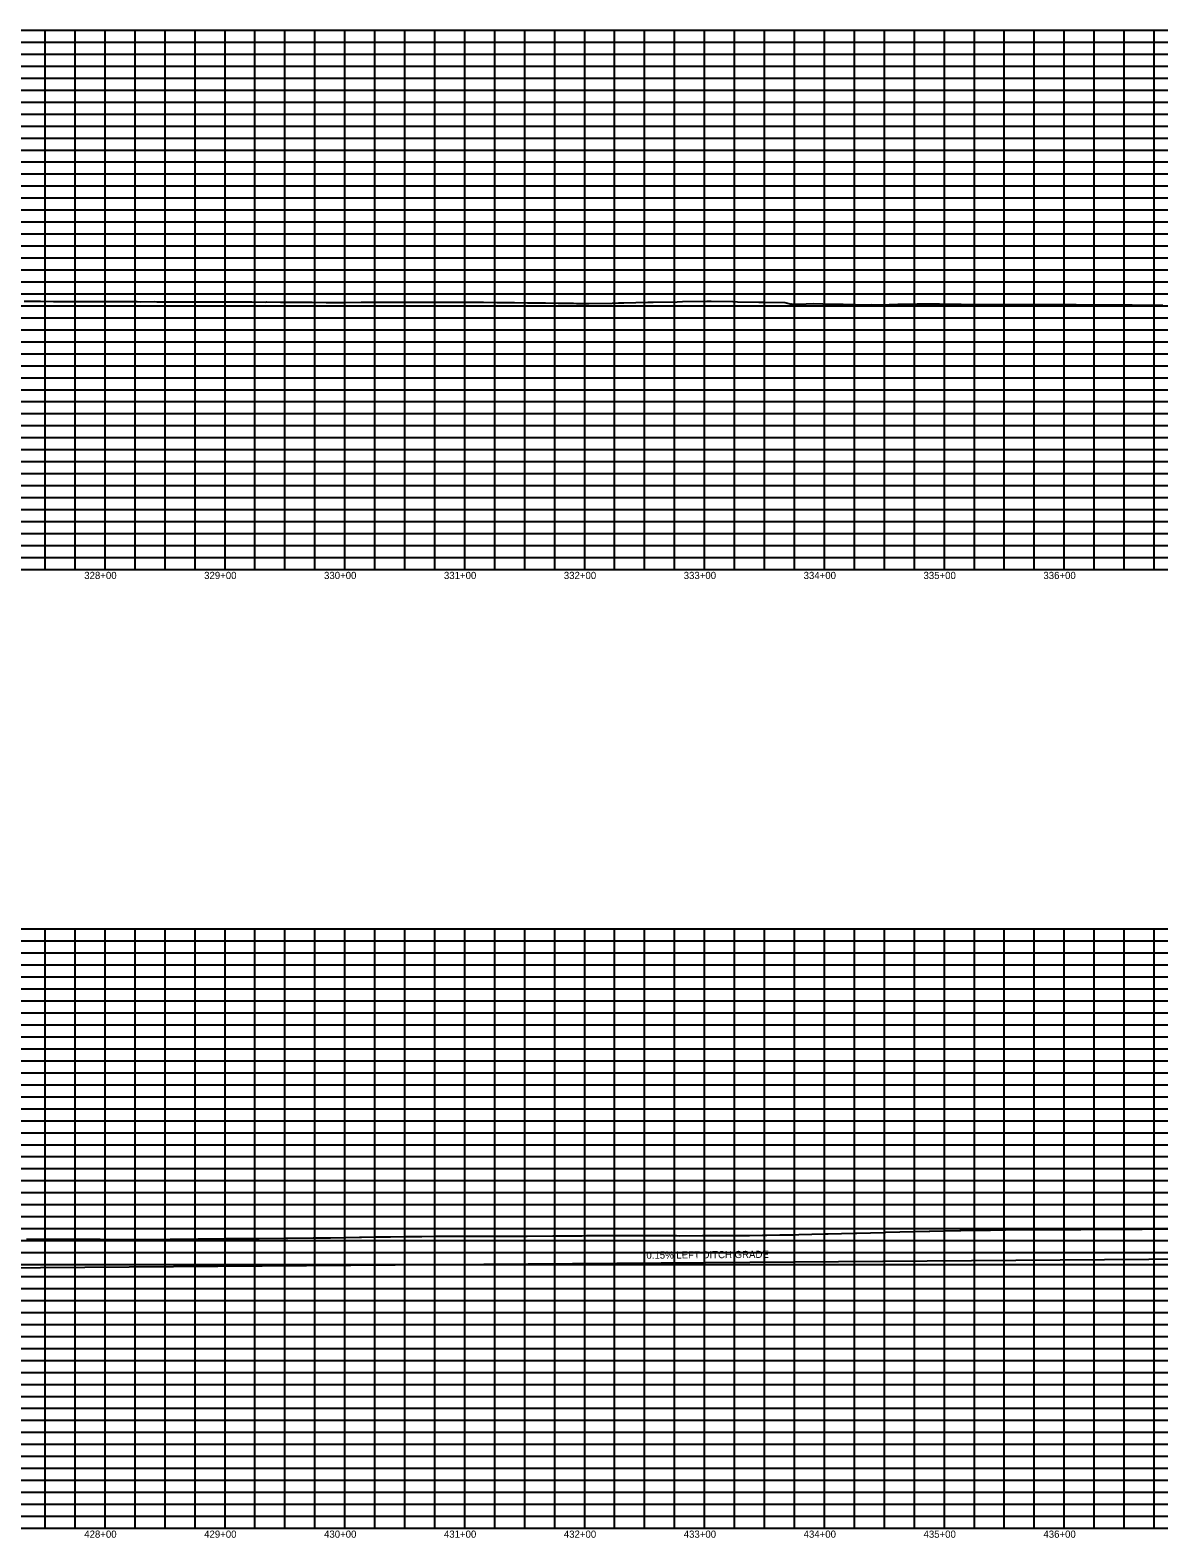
# Model space of a CAD drawing. Extents: x 1399671 to 1408349, y 1930471 to 1933387.
# Drawn here: x 1403062 to 1404003, y 1930471 to 1931729 of the extents above; entities that cross this region are included whole.
import ezdxf

# ---------------------------------------------------------------- set-up
doc = ezdxf.new("R2010")
doc.units = 0
for name, color, linetype in [('R_Exist Surface', 7, 'Continuous'), ('R_Grid', 7, 'Continuous'), ('R_Grid Annot', 7, 'Continuous'), ('R_Vert Alg', 7, 'Continuous'), ('R_Vert Alg Annot', 7, 'Continuous')]:
    doc.layers.add(name, color=color, linetype=linetype)

msp = doc.modelspace()

# ---------------------------------------------------------------- linework, layer by layer
at = {"layer": 'R_Exist Surface'}
for points in [[(1403056.7, 1931502.4), (1403067.6, 1931502.4), (1403070.2, 1931502.4), (1403081.2, 1931502.3), (1403083.8, 1931502.3), (1403094.8, 1931502.3), (1403097.4, 1931502.2), (1403108.8, 1931502.2), (1403111.4, 1931502.2), (1403122.9, 1931502.2), (1403125.4, 1931502.1), (1403136.9, 1931502.1), (1403139.4, 1931502.1), (1403150.9, 1931502.1), (1403153.4, 1931502), (1403165, 1931502.1), (1403167.4, 1931502), (1403179, 1931502), (1403181.4, 1931502), (1403193, 1931502), (1403204.8, 1931502), (1403207.1, 1931502), (1403217.8, 1931501.9), (1403219.7, 1931501.9), (1403230.7, 1931501.8), (1403232.4, 1931501.9), (1403243.5, 1931501.8), (1403245.1, 1931501.8), (1403246.6, 1931501.8), (1403257.8, 1931501.7), (1403259.1, 1931501.8), (1403270.4, 1931501.7), (1403271.7, 1931501.7), (1403283.1, 1931501.6), (1403284.2, 1931501.6), (1403295.8, 1931501.5), (1403296.8, 1931501.5), (1403308.5, 1931501.4), (1403309.5, 1931501.4), (1403323.1, 1931501.4), (1403324.2, 1931501.4), (1403337.7, 1931501.5), (1403339, 1931501.5), (1403352.3, 1931501.5), (1403353.7, 1931501.5), (1403367, 1931501.6), (1403368.4, 1931501.5), (1403381.6, 1931501.6), (1403383.1, 1931501.6), (1403396.2, 1931501.6), (1403397.8, 1931501.6), (1403410.8, 1931501.7), (1403412.5, 1931501.7), (1403425.4, 1931501.7), (1403427.1, 1931501.7), (1403438.2, 1931501.6), (1403439.9, 1931501.5), (1403451, 1931501.4), (1403452.8, 1931501.4), (1403463.8, 1931501.3), (1403465.7, 1931501.3), (1403476.5, 1931501.2), (1403478.7, 1931501.1), (1403489.3, 1931501), (1403491.6, 1931501), (1403502.1, 1931500.9), (1403504.5, 1931500.8), (1403514.9, 1931500.7), (1403517.5, 1931500.6), (1403527.7, 1931500.6), (1403547.2, 1931500.9), (1403552.3, 1931501.1), (1403556.9, 1931501.2), (1403576.9, 1931501.5), (1403581.3, 1931501.7), (1403601.4, 1931502), (1403605.8, 1931502.1), (1403626, 1931502.5), (1403629.7, 1931502.4), (1403647.8, 1931502.1), (1403651.7, 1931502), (1403669.4, 1931501.7), (1403673.6, 1931501.6), (1403691, 1931501.3), (1403695.7, 1931500.1), (1403696.3, 1931500), (1403697.1, 1931500.2), (1403703, 1931500), (1403714.7, 1931500.5), (1403722.7, 1931500.2), (1403731.6, 1931499.9), (1403739.8, 1931500), (1403750, 1931499.6), (1403755, 1931499.5), (1403763.8, 1931499.8), (1403770.4, 1931499.5), (1403778.2, 1931499.7), (1403785.5, 1931500), (1403794.4, 1931500), (1403801.6, 1931500.2), (1403810.9, 1931500.2), (1403820.1, 1931500.1), (1403830.1, 1931499.9), (1403838.3, 1931499.9), (1403848.7, 1931499.8), (1403856.3, 1931499.8), (1403867.1, 1931499.7), (1403872.9, 1931499.7), (1403881.6, 1931499.6), (1403888.9, 1931499.7), (1403896.5, 1931499.6), (1403905.2, 1931499.6), (1403912, 1931499.6), (1403917.6, 1931499.6), (1403927.8, 1931499.6), (1403934.2, 1931499.6), (1403946, 1931499.5), (1403953.6, 1931499.5), (1403963.6, 1931499.4), (1403972.4, 1931499.3), (1403980.8, 1931499.3), (1403990.5, 1931499.2), (1403998.1, 1931499.2), (1404006.3, 1931499.2)], [(1403058.5, 1930719.7), (1403069.5, 1930719.7), (1403071.1, 1930719.7), (1403082.2, 1930719.7), (1403083.8, 1930719.7), (1403094.9, 1930719.7), (1403096.5, 1930719.7), (1403107.5, 1930719.7), (1403118.6, 1930719.7), (1403120.2, 1930719.7), (1403131.3, 1930719.6), (1403133, 1930719.6), (1403144, 1930719.6), (1403145.7, 1930719.6), (1403156.7, 1930719.5), (1403158.4, 1930719.5), (1403178.5, 1930719.8), (1403181.7, 1930719.8), (1403201.8, 1930720.1), (1403204.9, 1930720.1), (1403224.1, 1930720.2), (1403227, 1930720.2), (1403229.9, 1930720.3), (1403249.2, 1930720.4), (1403252.6, 1930720.4), (1403273.5, 1930720.6), (1403276.7, 1930720.6), (1403297.8, 1930720.8), (1403299.3, 1930720.8), (1403310.6, 1930721), (1403312.2, 1930721), (1403323.4, 1930721.2), (1403325.1, 1930721.2), (1403336.3, 1930721.4), (1403338.1, 1930721.4), (1403349.1, 1930721.6), (1403351.1, 1930721.6), (1403362.2, 1930721.7), (1403373.5, 1930721.9), (1403375.4, 1930721.9), (1403386.6, 1930722), (1403388.5, 1930722), (1403399.8, 1930722.2), (1403401.7, 1930722.2), (1403421.4, 1930722.2), (1403424.7, 1930722.2), (1403444.3, 1930722.2), (1403447.6, 1930722.2), (1403451.4, 1930722.3), (1403472.6, 1930722.3), (1403476.3, 1930722.3), (1403497.5, 1930722.4), (1403501.2, 1930722.4), (1403522.1, 1930722.6), (1403525.6, 1930722.7), (1403546.6, 1930722.9), (1403548.7, 1930722.9), (1403560.7, 1930722.8), (1403562.9, 1930722.8), (1403574.9, 1930722.8), (1403586.7, 1930722.7), (1403589, 1930722.7), (1403600.8, 1930722.7), (1403603.1, 1930722.6), (1403622.4, 1930722.7), (1403626.1, 1930722.7), (1403645.5, 1930722.7), (1403649, 1930722.8), (1403659.9, 1930722.9), (1403661.7, 1930722.9), (1403672.6, 1930723.1), (1403674.4, 1930723.1), (1403676, 1930723.1), (1403687.1, 1930723.3), (1403688.6, 1930723.3), (1403699.7, 1930723.5), (1403702.7, 1930723.6), (1403724.6, 1930724.1), (1403727.3, 1930724.2), (1403749.5, 1930724.7), (1403751.3, 1930724.7), (1403774.1, 1930725.4), (1403775.4, 1930725.5), (1403798.8, 1930726.2), (1403799.5, 1930726.2), (1403811.5, 1930726.4), (1403812.1, 1930726.4), (1403824.3, 1930726.7), (1403825, 1930726.7), (1403837.1, 1930727), (1403837.8, 1930727), (1403849.9, 1930727.2), (1403862.3, 1930727.4), (1403862.6, 1930727.4), (1403875, 1930727.5), (1403875.2, 1930727.5), (1403887.7, 1930727.7), (1403887.9, 1930727.7), (1403900.4, 1930727.9), (1403900.5, 1930727.9), (1403912.8, 1930727.9), (1403913.2, 1930727.9), (1403925.6, 1930727.9), (1403937.8, 1930727.9), (1403938.4, 1930728), (1403950.6, 1930728), (1403950.9, 1930728), (1403963.5, 1930728.1), (1403976, 1930728.1), (1403976.4, 1930728.1), (1403988.9, 1930728.2), (1403989.3, 1930728.2), (1404001.8, 1930728.3), (1404002.2, 1930728.3), (1404025.6, 1930728.2)]]:
    msp.add_lwpolyline(points, dxfattribs=at)
at = {"layer": 'R_Grid'}
for p, q in [((1400324.2, 1931728.6), (1408324.2, 1931728.6)), ((1400324.2, 1931728.6), (1408324.2, 1931728.6)), ((1403074.2, 1931278.6), (1403074.2, 1931728.6)), ((1403099.2, 1931278.6), (1403099.2, 1931728.6)), ((1403124.2, 1931278.6), (1403124.2, 1931728.6)), ((1403149.2, 1931278.6), (1403149.2, 1931728.6)), ((1403174.2, 1931278.6), (1403174.2, 1931728.6)), ((1403199.2, 1931278.6), (1403199.2, 1931728.6)), ((1403224.2, 1931278.6), (1403224.2, 1931728.6)), ((1403249.2, 1931278.6), (1403249.2, 1931728.6)), ((1403274.2, 1931278.6), (1403274.2, 1931728.6)), ((1403299.2, 1931278.6), (1403299.2, 1931728.6)), ((1403324.2, 1931278.6), (1403324.2, 1931728.6)), ((1403349.2, 1931278.6), (1403349.2, 1931728.6)), ((1403374.2, 1931278.6), (1403374.2, 1931728.6)), ((1403399.2, 1931278.6), (1403399.2, 1931728.6)), ((1403424.2, 1931278.6), (1403424.2, 1931728.6)), ((1403449.2, 1931278.6), (1403449.2, 1931728.6)), ((1403474.2, 1931278.6), (1403474.2, 1931728.6)), ((1403499.2, 1931278.6), (1403499.2, 1931728.6)), ((1403524.2, 1931278.6), (1403524.2, 1931728.6)), ((1403549.2, 1931278.6), (1403549.2, 1931728.6)), ((1403574.2, 1931278.6), (1403574.2, 1931728.6)), ((1403599.2, 1931278.6), (1403599.2, 1931728.6)), ((1403624.2, 1931278.6), (1403624.2, 1931728.6)), ((1403649.2, 1931278.6), (1403649.2, 1931728.6)), ((1403674.2, 1931278.6), (1403674.2, 1931728.6)), ((1403699.2, 1931278.6), (1403699.2, 1931728.6)), ((1403724.2, 1931278.6), (1403724.2, 1931728.6)), ((1403749.2, 1931278.6), (1403749.2, 1931728.6)), ((1403774.2, 1931278.6), (1403774.2, 1931728.6)), ((1403799.2, 1931278.6), (1403799.2, 1931728.6)), ((1403824.2, 1931278.6), (1403824.2, 1931728.6)), ((1403849.2, 1931278.6), (1403849.2, 1931728.6)), ((1403874.2, 1931278.6), (1403874.2, 1931728.6)), ((1403899.2, 1931278.6), (1403899.2, 1931728.6)), ((1403924.2, 1931278.6), (1403924.2, 1931728.6)), ((1403949.2, 1931278.6), (1403949.2, 1931728.6)), ((1403974.2, 1931278.6), (1403974.2, 1931728.6)), ((1403999.2, 1931278.6), (1403999.2, 1931728.6)), ((1400324.2, 1931718.6), (1408324.2, 1931718.6)), ((1400324.2, 1931708.6), (1408324.2, 1931708.6)), ((1400324.2, 1931698.6), (1408324.2, 1931698.6)), ((1400324.2, 1931688.6), (1408324.2, 1931688.6)), ((1400324.2, 1931678.6), (1408324.2, 1931678.6)), ((1400324.2, 1931668.6), (1408324.2, 1931668.6)), ((1400324.2, 1931658.6), (1408324.2, 1931658.6)), ((1400324.2, 1931648.6), (1408324.2, 1931648.6)), ((1400324.2, 1931638.6), (1408324.2, 1931638.6)), ((1400324.2, 1931628.6), (1408324.2, 1931628.6)), ((1400324.2, 1931618.6), (1408324.2, 1931618.6)), ((1400324.2, 1931608.6), (1408324.2, 1931608.6)), ((1400324.2, 1931598.6), (1408324.2, 1931598.6)), ((1400324.2, 1931588.6), (1408324.2, 1931588.6)), ((1400324.2, 1931578.6), (1408324.2, 1931578.6)), ((1400324.2, 1931568.6), (1408324.2, 1931568.6)), ((1400324.2, 1931558.6), (1408324.2, 1931558.6)), ((1400324.2, 1931548.6), (1408324.2, 1931548.6)), ((1400324.2, 1931538.6), (1408324.2, 1931538.6)), ((1400324.2, 1931528.6), (1408324.2, 1931528.6)), ((1400324.2, 1931518.6), (1408324.2, 1931518.6)), ((1400324.2, 1931508.6), (1408324.2, 1931508.6)), ((1400324.2, 1931498.6), (1408324.2, 1931498.6)), ((1400324.2, 1931488.6), (1408324.2, 1931488.6)), ((1400324.2, 1931478.6), (1408324.2, 1931478.6)), ((1400324.2, 1931468.6), (1408324.2, 1931468.6)), ((1400324.2, 1931458.6), (1408324.2, 1931458.6)), ((1400324.2, 1931448.6), (1408324.2, 1931448.6)), ((1400324.2, 1931438.6), (1408324.2, 1931438.6)), ((1400324.2, 1931428.6), (1408324.2, 1931428.6)), ((1400324.2, 1931418.6), (1408324.2, 1931418.6)), ((1400324.2, 1931408.6), (1408324.2, 1931408.6)), ((1400324.2, 1931398.6), (1408324.2, 1931398.6)), ((1400324.2, 1931388.6), (1408324.2, 1931388.6)), ((1400324.2, 1931378.6), (1408324.2, 1931378.6)), ((1400324.2, 1931368.6), (1408324.2, 1931368.6)), ((1400324.2, 1931358.6), (1408324.2, 1931358.6)), ((1400324.2, 1931348.6), (1408324.2, 1931348.6)), ((1400324.2, 1931338.6), (1408324.2, 1931338.6)), ((1400324.2, 1931328.6), (1408324.2, 1931328.6)), ((1400324.2, 1931318.6), (1408324.2, 1931318.6)), ((1400324.2, 1931308.6), (1408324.2, 1931308.6)), ((1400324.2, 1931298.6), (1408324.2, 1931298.6)), ((1400324.2, 1931288.6), (1408324.2, 1931288.6)), ((1400324.2, 1931278.6), (1408324.2, 1931278.6)), ((1400324.2, 1930978.6), (1407124.2, 1930978.6)), ((1400324.2, 1930978.6), (1407124.2, 1930978.6)), ((1403074.2, 1930478.6), (1403074.2, 1930978.6)), ((1403099.2, 1930478.6), (1403099.2, 1930978.6)), ((1403124.2, 1930478.6), (1403124.2, 1930978.6)), ((1403149.2, 1930478.6), (1403149.2, 1930978.6)), ((1403174.2, 1930478.6), (1403174.2, 1930978.6)), ((1403199.2, 1930478.6), (1403199.2, 1930978.6)), ((1403224.2, 1930478.6), (1403224.2, 1930978.6)), ((1403249.2, 1930478.6), (1403249.2, 1930978.6)), ((1403274.2, 1930478.6), (1403274.2, 1930978.6)), ((1403299.2, 1930478.6), (1403299.2, 1930978.6)), ((1403324.2, 1930478.6), (1403324.2, 1930978.6)), ((1403349.2, 1930478.6), (1403349.2, 1930978.6)), ((1403374.2, 1930478.6), (1403374.2, 1930978.6)), ((1403399.2, 1930478.6), (1403399.2, 1930978.6)), ((1403424.2, 1930478.6), (1403424.2, 1930978.6)), ((1403449.2, 1930478.6), (1403449.2, 1930978.6)), ((1403474.2, 1930478.6), (1403474.2, 1930978.6)), ((1403499.2, 1930478.6), (1403499.2, 1930978.6)), ((1403524.2, 1930478.6), (1403524.2, 1930978.6)), ((1403549.2, 1930478.6), (1403549.2, 1930978.6)), ((1403574.2, 1930478.6), (1403574.2, 1930978.6)), ((1403599.2, 1930478.6), (1403599.2, 1930978.6)), ((1403624.2, 1930478.6), (1403624.2, 1930978.6)), ((1403649.2, 1930478.6), (1403649.2, 1930978.6)), ((1403674.2, 1930478.6), (1403674.2, 1930978.6)), ((1403699.2, 1930478.6), (1403699.2, 1930978.6)), ((1403724.2, 1930478.6), (1403724.2, 1930978.6)), ((1403749.2, 1930478.6), (1403749.2, 1930978.6)), ((1403774.2, 1930478.6), (1403774.2, 1930978.6)), ((1403799.2, 1930478.6), (1403799.2, 1930978.6)), ((1403824.2, 1930478.6), (1403824.2, 1930978.6)), ((1403849.2, 1930478.6), (1403849.2, 1930978.6)), ((1403874.2, 1930478.6), (1403874.2, 1930978.6)), ((1403899.2, 1930478.6), (1403899.2, 1930978.6)), ((1403924.2, 1930478.6), (1403924.2, 1930978.6)), ((1403949.2, 1930478.6), (1403949.2, 1930978.6)), ((1403974.2, 1930478.6), (1403974.2, 1930978.6)), ((1403999.2, 1930478.6), (1403999.2, 1930978.6)), ((1400324.2, 1930968.6), (1407124.2, 1930968.6)), ((1400324.2, 1930958.6), (1407124.2, 1930958.6)), ((1400324.2, 1930948.6), (1407124.2, 1930948.6)), ((1400324.2, 1930938.6), (1407124.2, 1930938.6)), ((1400324.2, 1930928.6), (1407124.2, 1930928.6)), ((1400324.2, 1930918.6), (1407124.2, 1930918.6)), ((1400324.2, 1930908.6), (1407124.2, 1930908.6)), ((1400324.2, 1930898.6), (1407124.2, 1930898.6)), ((1400324.2, 1930888.6), (1407124.2, 1930888.6)), ((1400324.2, 1930878.6), (1407124.2, 1930878.6)), ((1400324.2, 1930868.6), (1407124.2, 1930868.6)), ((1400324.2, 1930858.6), (1407124.2, 1930858.6)), ((1400324.2, 1930848.6), (1407124.2, 1930848.6)), ((1400324.2, 1930838.6), (1407124.2, 1930838.6)), ((1400324.2, 1930828.6), (1407124.2, 1930828.6)), ((1400324.2, 1930818.6), (1407124.2, 1930818.6)), ((1400324.2, 1930808.6), (1407124.2, 1930808.6)), ((1400324.2, 1930798.6), (1407124.2, 1930798.6)), ((1400324.2, 1930788.6), (1407124.2, 1930788.6)), ((1400324.2, 1930778.6), (1407124.2, 1930778.6)), ((1400324.2, 1930768.6), (1407124.2, 1930768.6)), ((1400324.2, 1930758.6), (1407124.2, 1930758.6)), ((1400324.2, 1930748.6), (1407124.2, 1930748.6)), ((1400324.2, 1930738.6), (1407124.2, 1930738.6)), ((1400324.2, 1930728.6), (1407124.2, 1930728.6)), ((1400324.2, 1930718.6), (1407124.2, 1930718.6)), ((1400324.2, 1930708.6), (1407124.2, 1930708.6)), ((1400324.2, 1930698.6), (1407124.2, 1930698.6)), ((1400324.2, 1930688.6), (1407124.2, 1930688.6)), ((1400324.2, 1930678.6), (1407124.2, 1930678.6)), ((1400324.2, 1930668.6), (1407124.2, 1930668.6)), ((1400324.2, 1930658.6), (1407124.2, 1930658.6)), ((1400324.2, 1930648.6), (1407124.2, 1930648.6)), ((1400324.2, 1930638.6), (1407124.2, 1930638.6)), ((1400324.2, 1930628.6), (1407124.2, 1930628.6)), ((1400324.2, 1930618.6), (1407124.2, 1930618.6)), ((1400324.2, 1930608.6), (1407124.2, 1930608.6)), ((1400324.2, 1930598.6), (1407124.2, 1930598.6)), ((1400324.2, 1930588.6), (1407124.2, 1930588.6)), ((1400324.2, 1930578.6), (1407124.2, 1930578.6)), ((1400324.2, 1930568.6), (1407124.2, 1930568.6)), ((1400324.2, 1930558.6), (1407124.2, 1930558.6)), ((1400324.2, 1930548.6), (1407124.2, 1930548.6)), ((1400324.2, 1930538.6), (1407124.2, 1930538.6)), ((1400324.2, 1930528.6), (1407124.2, 1930528.6)), ((1400324.2, 1930518.6), (1407124.2, 1930518.6)), ((1400324.2, 1930508.6), (1407124.2, 1930508.6)), ((1400324.2, 1930498.6), (1407124.2, 1930498.6)), ((1400324.2, 1930488.6), (1407124.2, 1930488.6)), ((1400324.2, 1930478.6), (1407124.2, 1930478.6))]:
    msp.add_line(p, q, dxfattribs=at)
at = {"layer": 'R_Vert Alg'}
msp.add_line((1402758.2, 1930693.8), (1404524.2, 1930707.1), dxfattribs=at)

# ---------------------------------------------------------------- texts
at = {"layer": 'R_Grid Annot'}
for s, p in [('328+00', (1403106.8, 1931270.6)), ('329+00', (1403206.8, 1931270.6)), ('330+00', (1403306.8, 1931270.6)), ('331+00', (1403406.8, 1931270.6)), ('332+00', (1403506.8, 1931270.6)), ('333+00', (1403606.8, 1931270.6)), ('334+00', (1403706.8, 1931270.6)), ('335+00', (1403806.8, 1931270.6)), ('336+00', (1403906.8, 1931270.6)), ('428+00', (1403106.8, 1930470.6)), ('429+00', (1403206.8, 1930470.6)), ('430+00', (1403306.8, 1930470.6)), ('431+00', (1403406.8, 1930470.6)), ('432+00', (1403506.8, 1930470.6)), ('433+00', (1403606.8, 1930470.6)), ('434+00', (1403706.8, 1930470.6)), ('435+00', (1403806.8, 1930470.6)), ('436+00', (1403906.8, 1930470.6))]:
    msp.add_text(s, height=6, dxfattribs=at).set_placement(p)
at = {"layer": 'R_Vert Alg Annot'}
msp.add_text('0.15% LEFT DITCH GRADE', height=6, rotation=0.4299, dxfattribs=at).set_placement((1403575.7, 1930703.4))

doc.saveas('drawing.dxf')
